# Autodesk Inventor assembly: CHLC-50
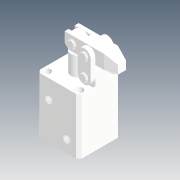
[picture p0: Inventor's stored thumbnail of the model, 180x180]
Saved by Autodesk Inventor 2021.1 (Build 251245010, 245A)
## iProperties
Created: 2019-04
Part Number: CHLC-50
Description: STEP AP214
Document SubType Name: Assembly
Designer: user
Title: CHLC-50.STEP
Revision Number: ÈÎºÎ
Sending System: SolidWorks 2016
Preprocessor: SwSTEP 2.0
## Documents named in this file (8)
- D:\Vault_2016\Projekty\Clamptek\Hydraulic\CHLC\CHLC-50\Inventor\CHLC-50\CHLC-50.iam
- D:\Vault_2016\Projekty\Clamptek\Hydraulic\CHLC\CHLC-50\Inventor\CHLC-50\CHLC-50-05.ipt
- D:\Vault_2016\Projekty\Clamptek\Hydraulic\CHLC\CHLC-50\Inventor\CHLC-50\CHLC-50-09.ipt
- D:\Vault_2016\Projekty\Clamptek\Hydraulic\CHLC\CHLC-50\Inventor\CHLC-50\CHLC-50-01.ipt
- D:\Vault_2016\Projekty\Clamptek\Hydraulic\CHLC\CHLC-50\Inventor\CHLC-50\CHLC-50-03.ipt
- D:\Vault_2016\Projekty\Clamptek\Hydraulic\CHLC\CHLC-50\Inventor\CHLC-50\CHLC-50-02.ipt
- D:\Vault_2016\Projekty\Clamptek\Hydraulic\CHLC\CHLC-50\Inventor\CHLC-50\CHLC-50-04.ipt
- D:\Vault_2016\Projekty\Clamptek\Hydraulic\CHLC\CHLC-50\Inventor\CHLC-50\CHLC-50-06.ipt
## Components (14 placed, 14 different names)
1. CHLC-50-05_1
2. CHLC-50-09_2
3. CHLC-50-01_3
4. CHLC-50-03_4
5. CHLC-50-03_5
6. CHLC-50-02_6
7. CHLC-50-04_7
8. CHLC-50-04_8
9. CHLC-50-06_9
10. CHLC-50-06_10
11. CHLC-50-06_11
12. CHLC-50-06_12
13. CHLC-50-06_13
14. CHLC-50-06_14
